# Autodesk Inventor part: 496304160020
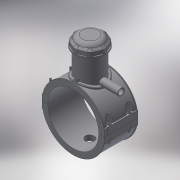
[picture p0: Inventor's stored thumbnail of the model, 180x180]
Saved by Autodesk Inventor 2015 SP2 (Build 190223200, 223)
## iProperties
Created: 2017-07
Part Number: 496304160020
Material: Generic
Description: PLASSON TAPPING SADDLE 160x20
Document SubType Name: Modeling
Designer: KIM
Mass: 999.441 g
Surface Area: 2210.49 cm^2
Volume: 999.441 cm^3
Density: 1 g/cm^3
Appearance: Default
Author: KIM
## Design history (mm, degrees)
derived "496304.ipt"
feature "Solid1::496304.ipt"
feature "Solid2::496304.ipt"
feature "Solid4::496304.ipt"
feature "Solid5::496304.ipt"
tag "TaggingFeature1"
body "Solid1"
body "Solid2"
other parameters: "B_" = 199, "L_" = 118, "d_t" = 6, "H_2" = 138, "H_1" = 21, "H_" = 118, "d1" = 182.4, "d148" = 2.4, "d160" = 2.4, "d169" = 3.375, "d192" = 6.3, "d2" = 199, "d4" = 118, "d5" = 0, "d6" = 0.1, "d8" = 0, "d19" = 6, "d20" = 6, "d21" = 70.8, "d23" = 0, "d24" = 35.4, "d26" = 0, "d29" = 3, "d30" = 53.33333, "d31" = 6, "d32" = 0, "d33" = 0, "d34" = 0.6, "d40" = 94.848, "d41" = 72, "d43" = 0, "d45" = 0, "d47" = 162, "d70" = 15, "d72" = 0, "d73" = 6, "d75" = 5, "d76" = 0, "d77" = 8, "d79" = 15, "d80" = 47.2, "d82" = 5 deg, "d84" = 4, "d85" = 14, "d86" = 0, "d87" = 3, "d88" = 0, "d89" = 1, "d90" = 1, "d91" = 94.4, "d92" = 0, "d93" = 0.5, "d94" = 84.21053, "d96" = 186.048, "d97" = 2.36, "d98" = 0, "d102" = 1.6, "d120" = 140 deg, "d121" = 24.228, "d122" = 20 deg, "d123" = 364.8, "d124" = 109.44, "d126" = 0, "d143" = 164.8, "d145" = 17.23077, "d149" = 2.4, "d150" = 18.95385, "d153" = 118, "d154" = 0, "d156" = 91.2, "d157" = 160 deg, "d159" = 4.48, "d161" = 2.4, "d162" = 70.8, "d163" = 0, "d167" = 16, "d168" = 88.97561, "d170" = 3.375, "d172" = 0, "d173" = 1, "d176" = 20 deg, "d177" = 11.2, "d178" = 22.4, "d180" = 0, "d183" = 8.96, "d184" = 8.96, "d185" = 38.35, "d186" = 38.35, "d187" = 91.2, "d188" = 6.72, "d189" = 11.2, "d190" = 0, "d191" = 136.8, "d193" = 6.3, "d194" = 4.13, "d195" = 90 deg, "d197" = 0, "d199" = 0, "d200" = 11.2, "d202" = 0, "d203" = 138, "d204" = 68.4, "d205" = 50.4, "d206" = 61.2, "d207" = 103.5, "d208" = 107.64, "d209" = 128.34, "d210" = 61.92, "d211" = 72, "d212" = 57.6, "d213" = 9.9, "d216" = 0, "d217" = 16, "d218" = 16, "d219" = 3.2, "d224" = 0, "d230" = 3.2, "d233" = 6, "d236" = 99.5, "d237" = 35.4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
